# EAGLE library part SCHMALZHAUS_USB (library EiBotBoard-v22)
USB Connectors USB-B-PTH is fully proven SKU : PRT-00139 USB-miniB is fully proven SKU : PRT-00587 USB-A-PCB is untested. USB-A-H is throughly reviewed, but untested. Spark Fun Electronics SKU : PRT-00437 USB-B-SMT is throughly reviewed, but untested. Needs silkscreen touching up. USB-A-S has not been used/tested USB-MB-H has not been used/tested
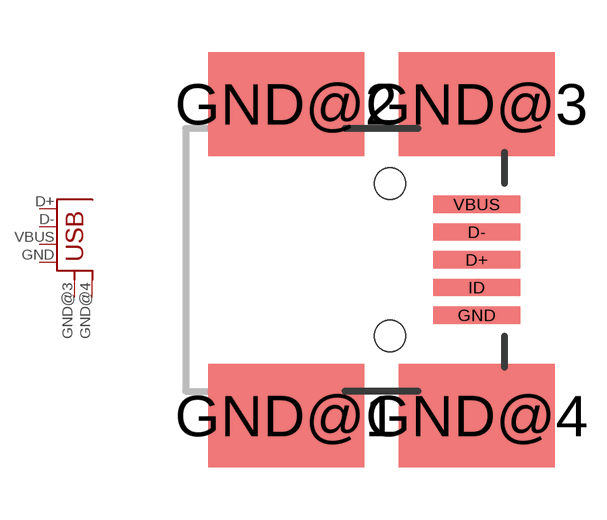
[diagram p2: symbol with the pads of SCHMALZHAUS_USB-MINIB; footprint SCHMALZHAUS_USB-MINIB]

Designator prefix X

## SCHMALZHAUS_USBSMD  [SCHMALZHAUS_USB-MINIB]
D+  D+
D-  D-
GND  GND
GND@3  GND  pwr
GND@4  GND  pwr
VBUS  VBUS

## Footprint SCHMALZHAUS_USB-MINIB (pad centres in mm)
USB Series Mini-B Surface Mounted
smd 2.5 x 0.5: D+ 2.5,0; D- 2.5,0.8; GND 2.5,-1.6; ID 2.5,-0.8; VBUS 2.5,1.6
smd 4.5 x 3: GND@1 -3,-4.5; GND@2 -3,4.5; GND@3 2.5,4.5; GND@4 2.5,-4.5
hole 0.9 at 0,2.2
hole 0.9 at 0,-2.2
